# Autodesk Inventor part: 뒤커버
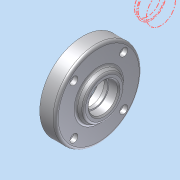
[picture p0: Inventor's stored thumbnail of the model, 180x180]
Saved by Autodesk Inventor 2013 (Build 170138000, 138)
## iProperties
Company: 한국ATC센터
Created: 2014-02
Part Number: 뒤커버
Document SubType Name: Modeling
Designer: KYOUNG IL JANG
Density: 2.71 g/cm^3
Mass: 97.9591 g
Surface Area: 115.525 cm^2
Volume: 36.1473 cm^3
Material: 알루미늄-6061
Vendor: CBT Solutions
Author: KYOUNG IL JANG
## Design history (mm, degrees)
sketch "스케치1"
  geometry: L1 (-10.5, 0)-(10.5, 0); L2 (10.5, 0)-(10.5, 22.5); L3 (10.5, 22.5)-(5.5, 22.5); L4 (5.5, 22.5)-(5.5, 32.5); L5 (5.5, 32.5)-(-6.5, 32.5); L6 (-6.5, 32.5)-(-6.5, 17.5); L7 (-6.5, 17.5)-(-10.5, 15.191); L8 (-10.5, 15.191)-(-10.5, 0); 2 further points
  constraints: 16 end point, 3 parallel, 3 perpendicular, 1 coincident, 1 horizontal, 1 midpoint
  dimensions: "d0" = 21 distance of L1.start L1.end; "d1" = 65 diameter of L5 L1; "d2" = 45 diameter of L3 L1; "d3" = 35 diameter of L6.end L1; "d4" = 120 deg angle of L7 L6; "d5" = 12 distance of L4.end L5.end; "d6" = 5 distance of L2.end L3.end
revolve "회전1" sketch "스케치1" stored, may be unused: angle "d7" = 90 deg
sketch "스케치2"
  geometry: L1 (0, 0)-(32.5, 0); L2 (0, 0)-(18.738, 18.738); 1 further point
  constraints: 4 end point, 1 horizontal, 1 horizontal alignment, 1 other
  dimensions: "d8" = 45 deg angle of L1 L2; "d9" = 26.5 distance of L1.start L2.end
hole "구멍1" sketch "스케치2" at (18.738, 18.738) diameter "d10" = 3.4; stored, may be unused: countersink angle "d14" = 90 deg, drill point angle "d16" = 118 deg; dims "d11" = 6, "d12" = 6, "d13" = 3.3, "d15" = 8
fillet "모깎기1" dims "d20" = 2
hole "구멍2" diameter "d23" = 15; stored, may be unused: countersink angle "d27" = 90 deg, drill point angle "d29" = 0 deg; dims "d21" = 10, "d22" = 10, "d24" = 6, "d25" = 35, "d26" = 11, "d28" = 14
chamfer "모따기1" distance "d39" = 1; stored, may be unused: second distance "d40" = 2, angle "d41" = 45 deg
fillet "모깎기2" dims "d42" = 0.3
hole "구멍4" diameter "d46" = 17; stored, may be unused: countersink angle "d50" = 90 deg, drill point angle "d52" = 118 deg; dims "d44" = 10, "d45" = 10, "d47" = 6, "d48" = 22, "d49" = 7.3, "d51" = 8
chamfer "모따기2" distance "d53" = 1; stored, may be unused: second distance "d54" = 2, angle "d55" = 45 deg
fillet "모깎기3" dims "d56" = 0.3
node "솔리드1"
pattern_circular "원형 패턴1" dims angle "d18" = 360 deg
